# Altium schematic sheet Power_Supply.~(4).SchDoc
size A4
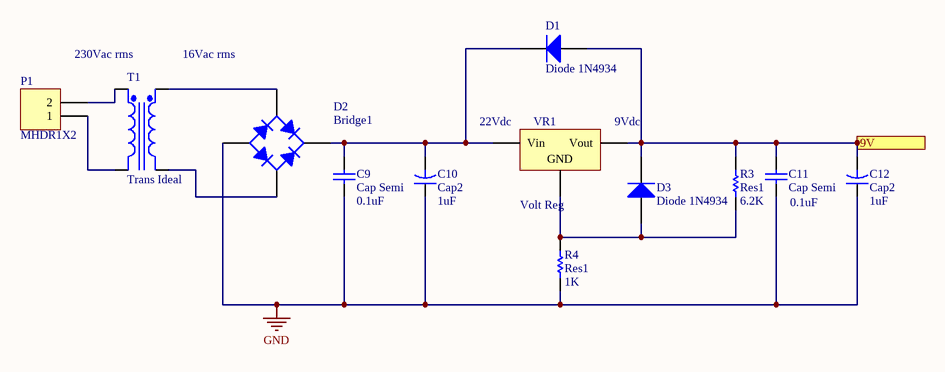
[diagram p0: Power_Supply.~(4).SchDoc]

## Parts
C9  Cap Semi  value 0.1uF  [C1206]
C10  Cap2  value 1uF  [CAPR5-4X5]
C11  Cap Semi  value 0.1uF  [C1206]
C12  Cap2  value 1uF  [CAPR5-4X5]
D1  Diode 1N4934  [DO-41]
D2  Bridge1  [D-38]
D3  Diode 1N4934  [DO-41]
P1  MHDR1X2  [MHDR1X2]
R3  Res1  value 6.2K  [AXIAL-0.3]
R4  Res1  value 1K  [AXIAL-0.3]
T1  Trans Ideal  [TRF_4]
VR1  Volt Reg  [D2PAK_N]

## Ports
9V (out)

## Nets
GND: C9.1 C10.1 C11.1 C12.1 D2.3(A) R4.1
9V: C11.2 C12.2 D1.1(A) D3.2(K) R3.1 VR1.3(Vout) ; port 9V
NetC9_2: C9.2 C10.2 D1.2(K) D2.1(K) VR1.1(Vin)
NetD2_2: D2.2(C) T1.4(Sec-)
NetD2_4: D2.4(C) T1.3(Sec+)
NetD3_1: D3.1(A) R3.2 R4.2 VR1.2(GND)
NetP1_1: P1.1 T1.2(Pri-)
NetP1_2: P1.2 T1.1(Pri+)

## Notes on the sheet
- 230Vac rms
- 16Vac rms
- (near VR1) 22Vdc
- (near VR1) 9Vdc

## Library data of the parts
C9 C11 = Cap Semi: Capacitor (Semiconductor SIM Model)
C10 C12 = Cap2: Capacitor
D1 D3 = Diode 1N4934: 1 Amp Fast Recovery Rectifier
D2 = Bridge1: Full Wave Diode Bridge
P1 = MHDR1X2: Header, 2-Pin
R3 R4 = Res1: Resistor
T1 = Trans Ideal: Transformer (Ideal)
VR1 = Volt Reg: Voltage Regulator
